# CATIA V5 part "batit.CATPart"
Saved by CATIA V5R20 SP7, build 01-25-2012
Part number: batit
Bounding box of the stored display mesh (mm): x -650 to 650, y 230 to 670, z -450 to 100
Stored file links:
  D:\thinkmotion-MPB\Dropbox\IAO_2012\IAO_2012_870_tsalesse\tsalesse\modele_catia\batit.CATPart
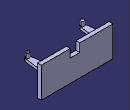
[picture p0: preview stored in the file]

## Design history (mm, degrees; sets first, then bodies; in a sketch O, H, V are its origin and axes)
Body1 (main body)
  Plane1 to Plane3: stored without definition
  Sketch1 on Plane1, origin (0, 0, -50), H (1, 0, 0), V (0, 1, 0)
    line L1 (0, 670) -> (650, 670)
    line L2 (650, 670) -> (650, 600)
    line L3 (650, 600) -> (0, 600)
    line L4 (0, 600) -> (0, 670)
    distance V L2 = 650
    length L1 = 650
    length L2 = 70
    distance L3 H = 600
    horizontal: L1 H, L3 H
    vertical: L2 V, L4 V
  Pad1: profile Sketch1, direction (0, 0, -1), length 400, opposite side length 150
  Plane4: stored without definition
  Sketch2 on Plane3, origin (0, 0, -50), H (1, 0, 0), V (0, 1, 0)
    arc A1 centre (500, 270) radius 40 from (460.3618, 264.6325) to (500, 230) ccw
    point P1 (500, 270)
    line L1 (419.6382, 565.3675) -> (460.3618, 264.6325)
    point P2 (500, 600)
    arc A2 centre (380, 560) radius 40 from (380, 600) to (419.6382, 565.3675) cw
    point P3 (380, 600)
    point P4 (419.6382, 565.3675)
    axis line L2 (500, 270) -> (500, 624.5527)
    point P6 (500, 270)
    point P7 (500, 624.5527)
    line L3 (500, 600) -> (380, 600)
    point P8 (500, 600)
    point P9 (460.3618, 264.6325)
    point P10 (500, 230)
    reference projected line E1 (0, 600) -> (600, 600) from edge [face of Pad1 from Sketch1.L3 | start face of Pad1]
    point P11 (620, 600)
    point P12 (500, 600)
    line L4 (500, 600) -> (620, 600)
    point P13 (580.3618, 565.3675)
    arc A3 centre (620, 560) radius 40 from (620, 600) to (580.3618, 565.3675) ccw
    point P15 (539.6382, 264.6325)
    line L5 (580.3618, 565.3675) -> (539.6382, 264.6325)
    point P16 (500, 230)
    arc A4 centre (500, 270) radius 40 from (539.6382, 264.6325) to (500, 230) cw
    radius A2 = 40
    distance P6 H = 270
    distance P6 V = 500
    distance P7 V = 500
    radius A1 = 40
    distance P1 H = 270
    distance P1 V = 500
    length L3 = 120
    tangency: L1 A1, A2 L1, L3 A2
    coincidence: P2 L3, P2 P8, L3 E1, P10 L2, P10 P16
    symmetry: P3 P11 L2, P8 P12 L2, L3 L4 L2, P4 P13 L2, A2 A3 L2, P9 P15 L2, L1 L5 L2, P10 P16 L2, A1 A4 L2
  Pad2: profile Sketch2, direction (0, 0, -1), length 50
  Sketch3 on Plane4, origin (0, 0, -50), H (1, 0, 0), V (0, 1, 0)
    circle A1 centre (500, 270) radius 30
    point P1 (500, 270)
    radius A1 = 30
    distance P1 H = 270
    distance P1 V = 500
  Pad3: profile Sketch3, direction (0, 0, 1), length 80
  Plane5: stored without definition
  Plane6: stored without definition
  Mirror1: of the body so far, about face of Pad1 from Sketch1.L4
  Line1 "axe_pivot_batit_sabot1": stored without definition
  Sketch4 on Plane6, origin (0, 0, 15), H (1, 0, 0), V (0, 1, 0)
    arc A1 centre (215, 560) radius 20 from (195.1946, 557.2165) to (234.8054, 557.2165) ccw
    point P1 (215, 560)
    reference projected point E1 (215, 560) from Line1
    line L1 (234.8054, 557.2165) -> (238.3986, 582.7835)
    point P2 (234.8054, 557.2165)
    point P3 (240.8182, 600)
    line L2 (195.1946, 557.2165) -> (191.6014, 582.7835)
    point P4 (195.1946, 557.2165)
    point P5 (189.1818, 600)
    line L3 (171.7961, 600) -> (258.2039, 600)
    point P6 (171.7961, 600)
    reference projected line E2 (650, 600) -> (0, 600) from edge [face of Pad1 | face of Pad1]
    axis line L4 (215, 554.5482) -> (215, 607.2597)
    arc A2 centre (258.2039, 580) radius 20 from (258.2039, 600) to (238.3986, 582.7835) ccw
    arc A3 centre (171.7961, 580) radius 20 from (191.6014, 582.7835) to (171.7961, 600) ccw
    point P13 (171.7961, 600)
    point P15 (195.1946, 557.2165)
    point P16 (234.8054, 557.2165)
    radius A1 = 20
    angle L1 L4 = 8
    angle L4 L2 = 8 {= Sketch4.angle(L1 L4)}
    radius A2 = 20
    radius A3 = 20 {= Sketch4.radius(A2)}
    coincidence: P1 E1, P2 A1, P4 A1, L3 E2, P5 L3, L3 P3, L1 P3, L2 P5, P13 P6, P15 L2, P16 L1, P2 P16, P4 P15
    tangency: L1 A1, L2 A1, A2 L3, A2 L1, A3 L2, L3 A3
    horizontal: L3 H
    vertical: L4 V
  Pad4: profile Sketch4, direction (0, 0, 1), length 15
  Line2 "axe_pivot_batit_sabot1": stored without definition
  RectPattern1: of Pad4, direction 1 instances 2, spacing 45, along Line2 reversed, direction 2 instances 2, spacing 365, along edge [face of Pad1 | face of Pad1]
  Sketch5 on face of Pad1, origin (0, 600, 0), H (1, 0, 0), V (0, 0, 1)
    line L1 (-48.2039, 100) -> (121.7961, 100)
    line L2 (121.7961, 100) -> (121.7961, -50)
    line L3 (121.7961, -50) -> (-48.2039, -50)
    line L4 (-48.2039, -50) -> (-48.2039, 100)
    reference projected line E1 (650, 100) -> (0, 100) from edge [face of Pad1 | face of Pad1]
    reference projected line E2 (380, -50) -> (419.6382, -50) from edge [face of Pad2 from Sketch2.A2 | start face of Pad2]
    reference projected line E3 (171.7961, -30) -> (171.7961, -15) from edge [face of RectPattern1 | face of Pad1]
    distance L2 E3 = 50
    length L1 = 170
    horizontal: L1 H, L3 H
    vertical: L2 V, L4 V
    coincidence: L1 E1, E2 L3
  Pocket1: profile Sketch5, direction (0, 1, 0), through (limit type 3)
  RectPattern2: of Pad4, direction 1 instances 2, spacing 430, along edge [face of Pad1 | end face of Pad4], direction 2 instances 2, spacing 45, along edge [face of Pad1 | face of Pocket1 from Sketch5.L2] reversed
